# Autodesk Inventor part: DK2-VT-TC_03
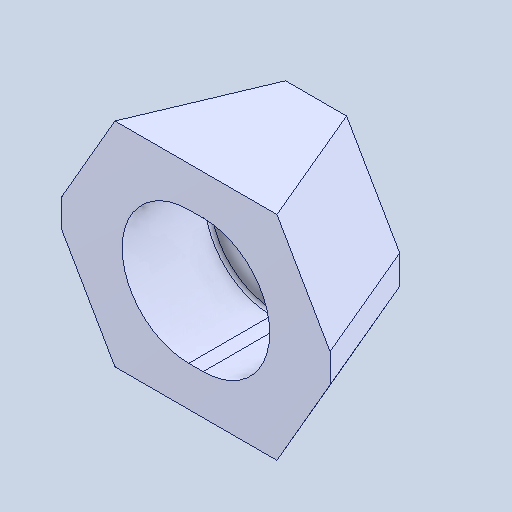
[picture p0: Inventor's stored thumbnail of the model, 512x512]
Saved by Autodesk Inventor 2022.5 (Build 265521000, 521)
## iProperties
Created: 2024-05
Part Number: DK2-VT-TC_03
Material: 一般
Document SubType Name: Modeling
Designer: ImaoCorp
Density: 1 g/cm^3
Appearance: 既定
Author: ImaoCorp
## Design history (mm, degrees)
feature "DK2-VT-TC_03"
node "ソリッド1"
